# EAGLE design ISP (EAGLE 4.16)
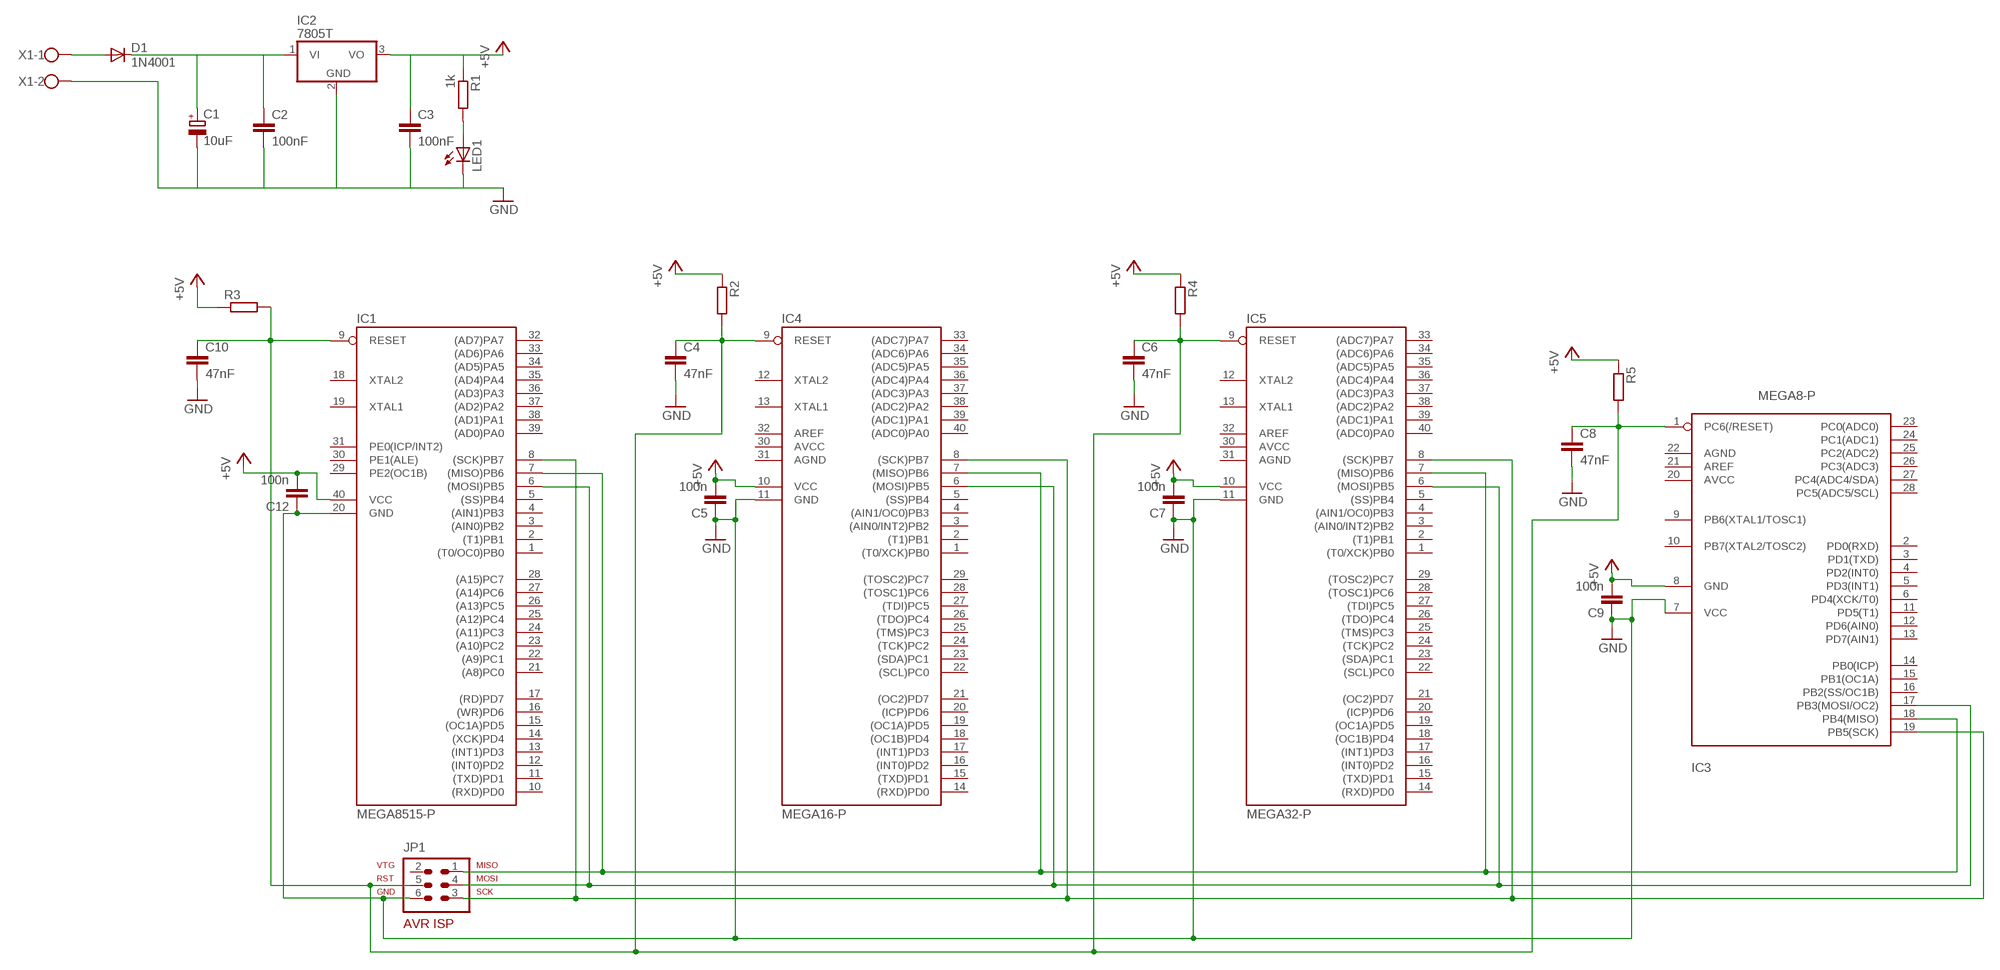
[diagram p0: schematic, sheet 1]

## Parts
C1  10uF  CPOL-EUE15-6AXIAL  [E15-6]
C2  100nF  C-EU025-024X044  [C025-024X044]
C3  100nF  C-EU025-024X044  [C025-024X044]
C4  47nF  C-EU025-024X044  [C025-024X044]
C5  100n  C-EU025-024X044  [C025-024X044]
C6  47nF  C-EU025-024X044  [C025-024X044]
C7  100n  C-EU025-024X044  [C025-024X044]
C8  47nF  C-EU025-024X044  [C025-024X044]
C9  100n  C-EU025-024X044  [C025-024X044]
C10  47nF  C-EU025-024X044  [C025-024X044]
C12  100n  C-EU025-024X044  [C025-024X044]
D1  1N4001  1N4004  [DO41-10]
IC1  MEGA8515-P  [DIL40]
IC2  7805T  [TO220H]
IC3  MEGA8-P  [DIL28-3]
IC4  MEGA16-P  [DIL40]
IC5  MEGA32-P  [DIL40]
JP1  AVR-ISP-6  [AVR-ISP-6]
LED1  LED5MM  [LED5MM]
R1  1k  R-EU_0204/7  [0204/7]
R2  R-EU_0207/10  [0207/10]
R3  R-EU_0207/10  [0207/10]
R4  R-EU_0207/10  [0207/10]
R5  R-EU_0207/10  [0207/10]
X1  W237-102  [W237-102]

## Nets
+5V: C3.1 C5.2 C7.2 C9.2 C12.2 IC1.40(VCC) IC2.3(VO) IC3.8(GND) IC4.10(VCC) IC5.10(VCC) R1.1 R2.1 R3.1 R4.1 R5.1
GND: C1.- C2.2 C3.2 C4.2 C5.1 C6.2 C7.1 C8.2 C9.1 C10.2 C12.1 IC1.20(GND) IC2.2(GND) IC3.7(VCC) IC4.11(GND) IC5.11(GND) JP1.6 LED1.K(C) X1.2
N$1: D1.A X1.1
N$2: C1.+ C2.1 D1.C IC2.1(VI)
N$4: LED1.A R1.2
N$5: IC1.7((MISO)PB6) IC3.18(PB4(MISO)) IC4.7((MISO)PB6) IC5.7((MISO)PB6) JP1.1
N$6: IC1.6((MOSI)PB5) IC3.17(PB3(MOSI/OC2)) IC4.6((MOSI)PB5) IC5.6((MOSI)PB5) JP1.4
N$7: IC1.8((SCK)PB7) IC3.19(PB5(SCK)) IC4.8((SCK)PB7) IC5.8((SCK)PB7) JP1.3
N$9: C4.1 C6.1 C8.1 C10.1 IC1.9(RESET) IC3.1(PC6(/RESET)) IC4.9(RESET) IC5.9(RESET) JP1.5 R2.2 R3.2 R4.2 R5.2
Unconnected: IC1.1((T0/OC0)PB0) IC1.2((T1)PB1) IC1.3((AIN0)PB2) IC1.4((AIN1)PB3) IC1.5((SS)PB4) IC1.10((RXD)PD0) IC1.11((TXD)PD1) IC1.12((INT0)PD2) IC1.13((INT1)PD3) IC1.14((XCK)PD4) IC1.15((OC1A)PD5) IC1.16((WR)PD6) IC1.17((RD)PD7) IC1.18(XTAL2) IC1.19(XTAL1) IC1.21((A8)PC0) IC1.22((A9)PC1) IC1.23((A10)PC2) IC1.24((A11)PC3) IC1.25((A12)PC4) IC1.26((A13)PC5) IC1.27((A14)PC6) IC1.28((A15)PC7) IC1.29(PE2(OC1B)) IC1.30(PE1(ALE)) IC1.31(PE0(ICP/INT2)) IC1.32((AD7)PA7) IC1.33((AD6)PA6) IC1.34((AD5)PA5) IC1.35((AD4)PA4) IC1.36((AD3)PA3) IC1.37((AD2)PA2) IC1.38((AD1)PA1) IC1.39((AD0)PA0) IC3.2(PD0(RXD)) IC3.3(PD1(TXD)) IC3.4(PD2(INT0)) IC3.5(PD3(INT1)) IC3.6(PD4(XCK/T0)) IC3.9(PB6(XTAL1/TOSC1)) IC3.10(PB7(XTAL2/TOSC2)) IC3.11(PD5(T1)) IC3.12(PD6(AIN0)) IC3.13(PD7(AIN1)) IC3.14(PB0(ICP)) IC3.15(PB1(OC1A)) IC3.16(PB2(SS/OC1B)) IC3.20(AVCC) IC3.21(AREF) IC3.22(AGND) IC3.23(PC0(ADC0)) IC3.24(PC1(ADC1)) IC3.25(PC2(ADC2)) IC3.26(PC3(ADC3)) IC3.27(PC4(ADC4/SDA)) IC3.28(PC5(ADC5/SCL)) IC4.1((T0/XCK)PB0) IC4.2((T1)PB1) IC4.3((AIN0/INT2)PB2) IC4.4((AIN1/OC0)PB3) IC4.5((SS)PB4) IC4.12(XTAL2) IC4.13(XTAL1) IC4.14((RXD)PD0) IC4.15((TXD)PD1) IC4.16((INT0)PD2) IC4.17((INT1)PD3) IC4.18((OC1B)PD4) IC4.19((OC1A)PD5) IC4.20((ICP)PD6) IC4.21((OC2)PD7) IC4.22((SCL)PC0) IC4.23((SDA)PC1) IC4.24((TCK)PC2) IC4.25((TMS)PC3) IC4.26((TDO)PC4) IC4.27((TDI)PC5) IC4.28((TOSC1)PC6) IC4.29((TOSC2)PC7) IC4.33((ADC7)PA7) IC4.34((ADC6)PA6) IC4.35((ADC5)PA5) IC4.36((ADC4)PA4) IC4.37((ADC3)PA3) IC4.38((ADC2)PA2) IC4.39((ADC1)PA1) IC4.40((ADC0)PA0) IC5.1((T0/XCK)PB0) IC5.2((T1)PB1) IC5.3((AIN0/INT2)PB2) IC5.4((AIN1/OC0)PB3) IC5.5((SS)PB4) IC5.12(XTAL2) IC5.13(XTAL1) IC5.14((RXD)PD0) IC5.15((TXD)PD1) IC5.16((INT0)PD2) IC5.17((INT1)PD3) IC5.18((OC1B)PD4) IC5.19((OC1A)PD5) IC5.20((ICP)PD6) IC5.21((OC2)PD7) IC5.22((SCL)PC0) IC5.23((SDA)PC1) IC5.24((TCK)PC2) IC5.25((TMS)PC3) IC5.26((TDO)PC4) IC5.27((TDI)PC5) IC5.28((TOSC1)PC6) IC5.29((TOSC2)PC7) IC5.33((ADC7)PA7) IC5.34((ADC6)PA6) IC5.35((ADC5)PA5) IC5.36((ADC4)PA4) IC5.37((ADC3)PA3) IC5.38((ADC2)PA2) IC5.39((ADC1)PA1) IC5.40((ADC0)PA0) JP1.2

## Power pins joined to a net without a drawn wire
AGND: IC4.31(AGND) IC5.31(AGND)
AREF: IC4.32(AREF) IC5.32(AREF)
AVCC: IC4.30(AVCC) IC5.30(AVCC)

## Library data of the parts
C1 = rcl:CPOL-EU: POLARIZED CAPACITOR, European symbol
C2-C10 C12 = rcl:C-EU: CAPACITOR, European symbol
D1 = diode:1N4004: DIODE
IC1 = atmel:MEGA8515-P: MICROCONTROLLER 8 Kbytes FLASH 512 bytes SRAM 512 bytes EEPROM USART 8-channel 10 bit ADC Source: avr.lbr
IC2 = linear:78*: Positive VOLTAGE REGULATOR Source: http://cache.national.com/ds/LM/LM78L05.pdf http://www.fairchildsemi.com/ds/LM/LM7805.pdf
IC3 = atmel:MEGA8-P: MICROCONTROLLER 8 Kbytes FLASH 1 kbytes SRAM 512 bytes EEPROM USART 4-channel 10 bit ADC 2-channel 8 bit ADC Source: avr.lbr
IC4 = atmel:MEGA16-P: MICROCONTROLLER 16 Kbytes FLASH 1 kbytes SRAM 512 bytes EEPROM USART 8-channel 10 bit ADC Source: avr.lbr
IC5 = atmel:MEGA32-P: MICROCONTROLLER 32 Kbytes FLASH 2 Kbytes SRAM 1 Kbytes EEPROM USART 8-channel 10 bit ADC Source: www.atmel.com .. doc2503.pdf
JP1 = atmel:AVR-ISP-6: AVR ISP-6 Serial Programming Header
LED1 = led:LED: LED
R1-R5 = rcl:R-EU_: RESISTOR, European symbol
X1 = con-wago-500:W237-102: WAGO SCREW CLAMP

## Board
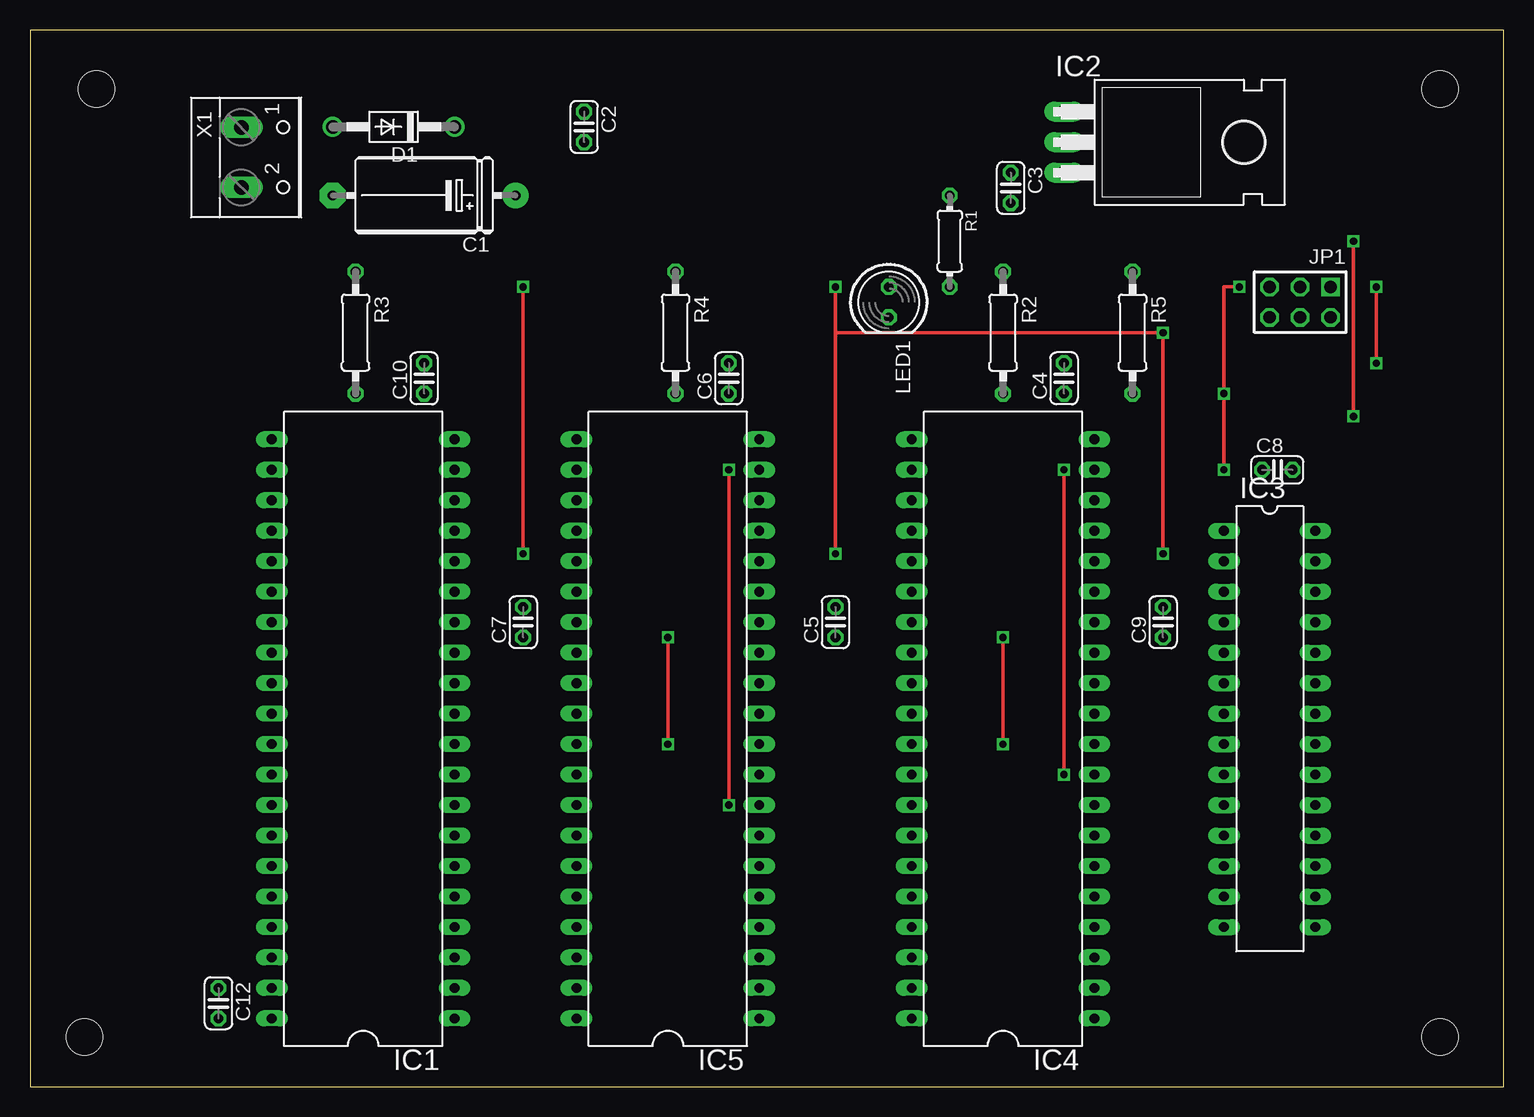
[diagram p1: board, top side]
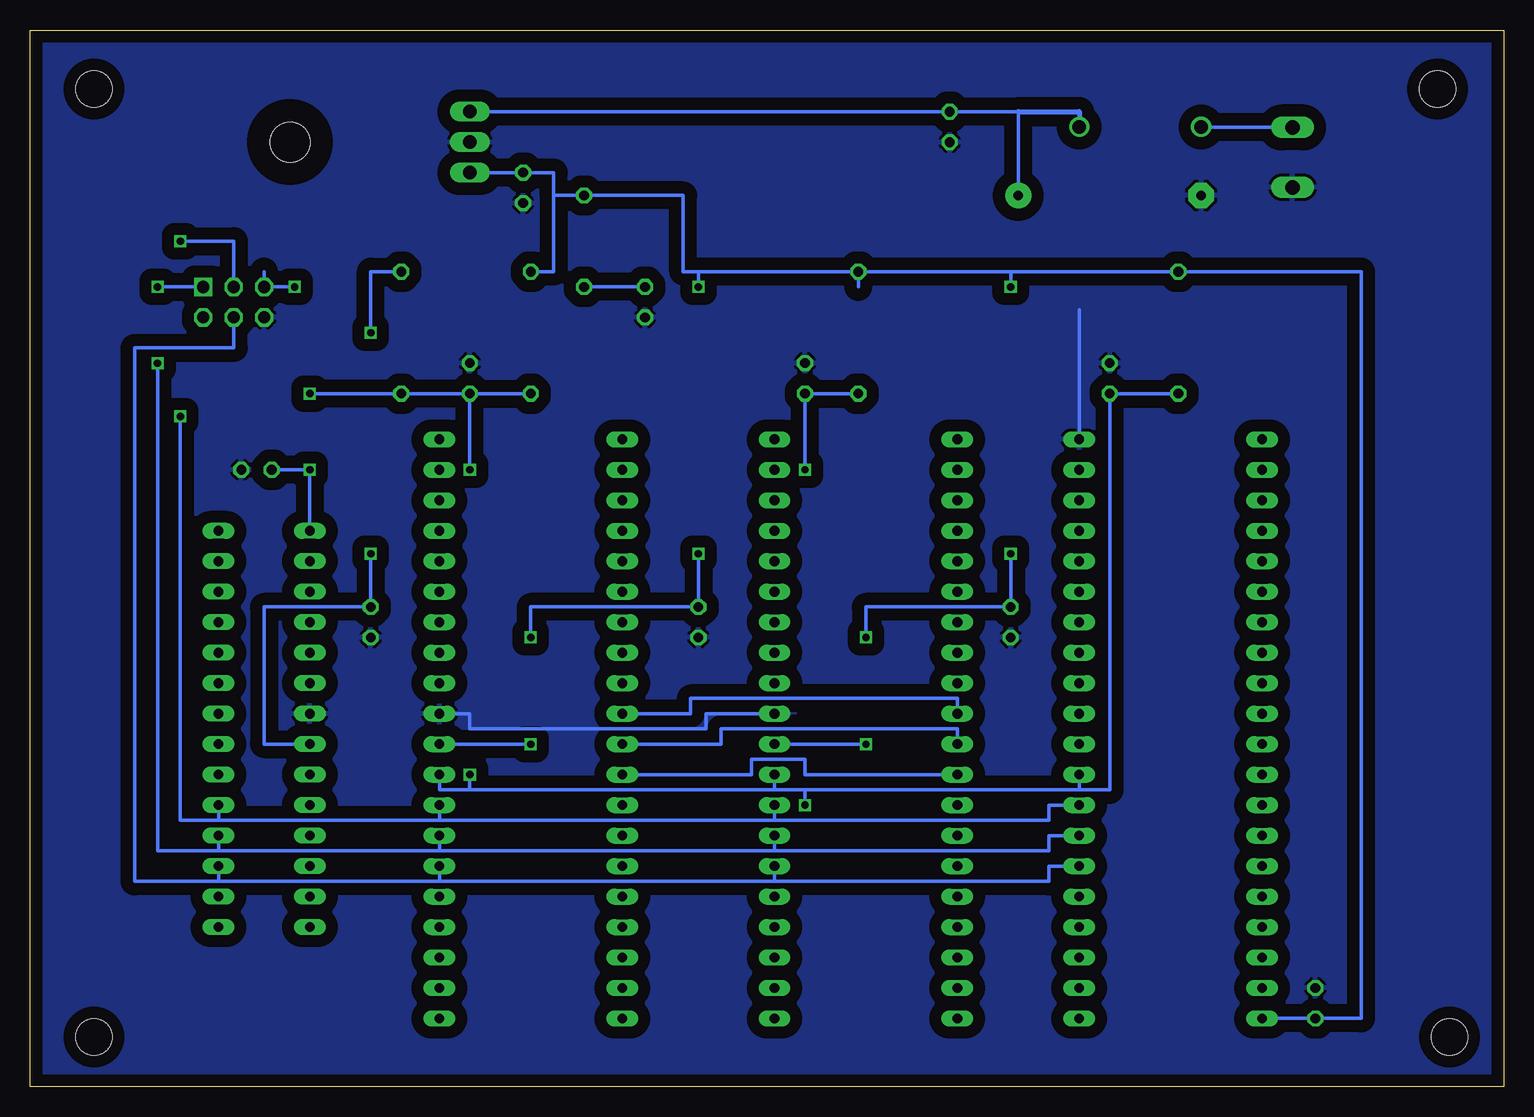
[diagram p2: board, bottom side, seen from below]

Size 122.86 x 88.08 mm. Coordinates in mm from the lower left corner, seen from the top.
Outline: 0,0 122.86,0 122.86,88.08 0,88.08 0,0
Copper layers (1*16): Top 0.035mm / dielectric 1.5mm / Bottom 0.035mm
Design rules "default": minimum track width 10mil, minimum drill 24mil, track to track 8mil, track to pad 8mil, pad to pad 8mil, via to via 8mil, smd to smd 8mil, copper to edge 40mil, drill to drill 8mil, minimum pad ring 10mil, minimum via ring 8mil, stop-mask expansion 4mil, vias tented up to drill 0mil, thermal gap 10mil
Holes 3 mm at 5.54,83.17 117.53,83.17 117.53,4.17 4.54,4.17

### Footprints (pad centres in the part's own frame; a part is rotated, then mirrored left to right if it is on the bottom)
E15-6 = drill 0.813 pad 2.159 round: + -7.62,0 | drill 0.813 pad 2.159 octagon: - 7.62,0
C025-024X044 = drill 0.813 octagon: 1 -1.27,0; 2 1.27,0
DO41-10 = drill 1.118 round: A 5.08,0; C -5.08,0
DIL40 = drill 0.813 long: 1 -24.13,-7.62; 2 -21.59,-7.62; 3 -19.05,-7.62; 4 -16.51,-7.62; 5 -13.97,-7.62; 6 -11.43,-7.62; 7 -8.89,-7.62; 8 -6.35,-7.62; 9 -3.81,-7.62; 10 -1.27,-7.62; 11 1.27,-7.62; 12 3.81,-7.62; 13 6.35,-7.62; 14 8.89,-7.62; 15 11.43,-7.62; 16 13.97,-7.62; 17 16.51,-7.62; 18 19.05,-7.62; 19 21.59,-7.62; 20 24.13,-7.62; 21 24.13,7.62; 22 21.59,7.62; 23 19.05,7.62; 24 16.51,7.62; 25 13.97,7.62; 26 11.43,7.62; 27 8.89,7.62; 28 6.35,7.62; 29 3.81,7.62; 30 1.27,7.62; 31 -1.27,7.62; 32 -3.81,7.62; 33 -6.35,7.62; 34 -8.89,7.62; 35 -11.43,7.62; 36 -13.97,7.62; 37 -16.51,7.62; 38 -19.05,7.62; 39 -21.59,7.62; 40 -24.13,7.62
TO220H = drill 1.118 long: 1 -2.54,-10.16; 2 0,-10.16; 3 2.54,-10.16 | hole 3.302: 0,4.826
DIL28-3 = drill 0.813 long: 1 -16.51,-3.81; 2 -13.97,-3.81; 3 -11.43,-3.81; 4 -8.89,-3.81; 5 -6.35,-3.81; 6 -3.81,-3.81; 7 -1.27,-3.81; 8 1.27,-3.81; 9 3.81,-3.81; 10 6.35,-3.81; 11 8.89,-3.81; 12 11.43,-3.81; 13 13.97,-3.81; 14 16.51,-3.81; 15 16.51,3.81; 16 13.97,3.81; 17 11.43,3.81; 18 8.89,3.81; 19 6.35,3.81; 20 3.81,3.81; 21 1.27,3.81; 22 -1.27,3.81; 23 -3.81,3.81; 24 -6.35,3.81; 25 -8.89,3.81; 26 -11.43,3.81; 27 -13.97,3.81; 28 -16.51,3.81
AVR-ISP-6 = drill 1.016 square: 1 -2.54,-1.27 | drill 1.016 octagon: 2 -2.54,1.27; 3 0,-1.27; 4 0,1.27; 5 2.54,-1.27; 6 2.54,1.27
LED5MM = drill 0.813 octagon: A -1.27,0; K 1.27,0
0204/7 = drill 0.813 octagon: 1 -3.81,0; 2 3.81,0
0207/10 = drill 0.813 octagon: 1 -5.08,0; 2 5.08,0
W237-102 = drill 1.194 long: 1 -2.5,-1.27; 2 2.5,-1.27

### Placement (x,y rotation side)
C1  32.86,74.29 180 top
C2  46.19,80 270 top
C3  81.75,74.92 270 top
C4  86.19,59.05 90 top
C5  67.14,38.73 90 top
C6  58.25,59.05 90 top
C7  41.11,38.73 90 top
C8  103.97,51.43 0 top
C9  94.45,38.73 90 top
C10  32.86,59.05 90 top
C12  15.71,6.98 270 top
D1  30.32,80 180 top
IC1  27.77,29.84 90 top
IC2  96.35,78.73 270 top
IC3  103.34,29.84 270 top
IC4  81.11,29.84 90 top
IC5  53.17,29.84 90 top
JP1  105.88,65.4 180 top
LED1  71.59,65.4 270 top
R1  76.67,70.48 270 top
R2  81.11,62.86 270 top
R3  27.14,62.86 270 top
R4  53.81,62.86 270 top
R5  91.91,62.86 270 top
X1  18.88,77.47 270 top

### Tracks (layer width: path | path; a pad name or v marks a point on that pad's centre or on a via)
+5V  (via drill 0.6)
  Top 0.305: v81.11,37.46 v81.11,28.57 | v67.14,66.67 67.14,62.86 | 67.14,62.86 v67.14,44.45 | v41.11,66.67 v41.11,44.45 | v53.17,37.46 v53.17,28.57 | v94.45,44.45 v94.45,62.86 67.14,62.86
  Bottom 0.305: R4.1 53.81,66.67 | v81.11,28.57 IC4.10 | IC1.40 C12.2 11.9,5.71 11.9,67.94 R3.1 41.11,67.94 | IC2.3 C3.1 79.21,76.2 79.21,74.29 | 79.21,74.29 R1.1 68.42,74.29 68.42,67.94 67.14,67.94 | R4.1 67.14,67.94 | R2.1 79.21,67.94 79.21,74.29 | 41.11,67.94 R4.1 | v67.14,44.45 C5.2 81.11,40 v81.11,37.46 | 67.14,67.94 v67.14,66.67 | v41.11,44.45 C7.2 53.17,40 v53.17,37.46 | 41.11,67.94 v41.11,66.67 | v53.17,28.57 IC5.10 | IC3.8 103.34,28.57 103.34,40 C9.2 v94.45,44.45 | R5.1 94.45,67.94 v94.45,62.86
AGND
  Bottom 0.305: IC5.31 45.56,29.84 65.24,29.84 65.24,28.57 IC4.31
AREF
  Bottom 0.305: IC5.32 58.25,26.03 58.25,27.3 62.7,27.3 62.7,26.03 IC4.32
AVCC
  Bottom 0.305: IC5.30 45.56,32.38 67.78,32.38 67.78,31.11 IC4.30
GND
  Bottom 0.305: IC1.20 35.39,64.77 | IC5.11 66.51,31.11 66.51,29.84 86.19,29.84 86.19,31.11 IC4.11
  pour Bottom (isolate 1.016): -0.16,87.45 122.39,87.45 122.39,0.63 -0.16,0.63
N$1
  Bottom 0.305: X1.1 25.23,79.97 D1.A
N$2
  Bottom 0.305: C1.+ 40.48,81.28 C2.1 IC2.1
  Bottom 0.406: 40.48,81.28 35.39,81.28 D1.C
N$4
  Bottom 0.305: LED1.A R1.2
N$5  (via drill 0.6)
  Top 0.305: v112.23,60.32 v112.23,66.67
  Bottom 0.305: IC1.7 37.94,20.95 37.94,19.68 60.8,19.68 | 60.8,19.68 IC5.7 | 60.8,19.68 88.73,19.68 | 88.73,19.68 IC4.7 | 88.73,19.68 107.15,19.68 | 107.15,19.68 IC3.18 | 107.15,19.68 112.23,19.68 v112.23,60.32 | v112.23,66.67 JP1.1
N$6
  Bottom 0.305: IC1.6 37.94,18.41 37.94,17.14 60.8,17.14 | 60.8,17.14 IC5.6 | 60.8,17.14 88.73,17.14 | 88.73,17.14 IC4.6 | 88.73,17.14 107.15,17.14 | 107.15,17.14 IC3.17 | 107.15,17.14 114.13,17.14 114.13,61.59 105.88,61.59 JP1.4
N$7  (via drill 0.6)
  Top 0.305: v110.33,55.88 v110.33,70.48
  Bottom 0.305: IC1.8 37.94,23.49 37.94,22.22 60.8,22.22 | 60.8,22.22 IC5.8 | 60.8,22.22 88.73,22.22 | 88.73,22.22 IC4.8 | 88.73,22.22 107.15,22.22 | 107.15,22.22 IC3.19 | 107.15,22.22 110.33,22.22 v110.33,55.88 | v110.33,70.48 105.88,70.48 JP1.3
N$9  (via drill 0.6)
  Top 0.305: v58.25,23.49 v58.25,51.43 | v86.19,26.03 v86.19,51.43 | v99.53,51.43 v99.53,57.78 99.53,66.67 v100.8,66.67
  Bottom 0.305: 35.39,24.76 32.86,24.76 C10.1 R3.2 | 57.62,24.76 60.8,24.76 | 103.34,67.94 JP1.5 v100.8,66.67 | 60.8,24.76 IC5.9 | 60.8,24.76 84.92,24.76 | 84.92,24.76 88.73,24.76 IC4.9 | 35.39,24.76 57.62,24.76 | 57.62,24.76 58.25,24.76 v58.25,23.49 | v58.25,51.43 C6.1 R4.2 | 35.39,24.76 IC1.9 | C4.1 R2.2 | v86.19,51.43 C4.1 | 84.92,24.76 86.19,24.76 v86.19,26.03 | IC3.1 v99.53,51.43 C8.1 | C4.1 R5.2 v99.53,57.78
